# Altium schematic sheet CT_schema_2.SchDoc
size 461 x 327 mm
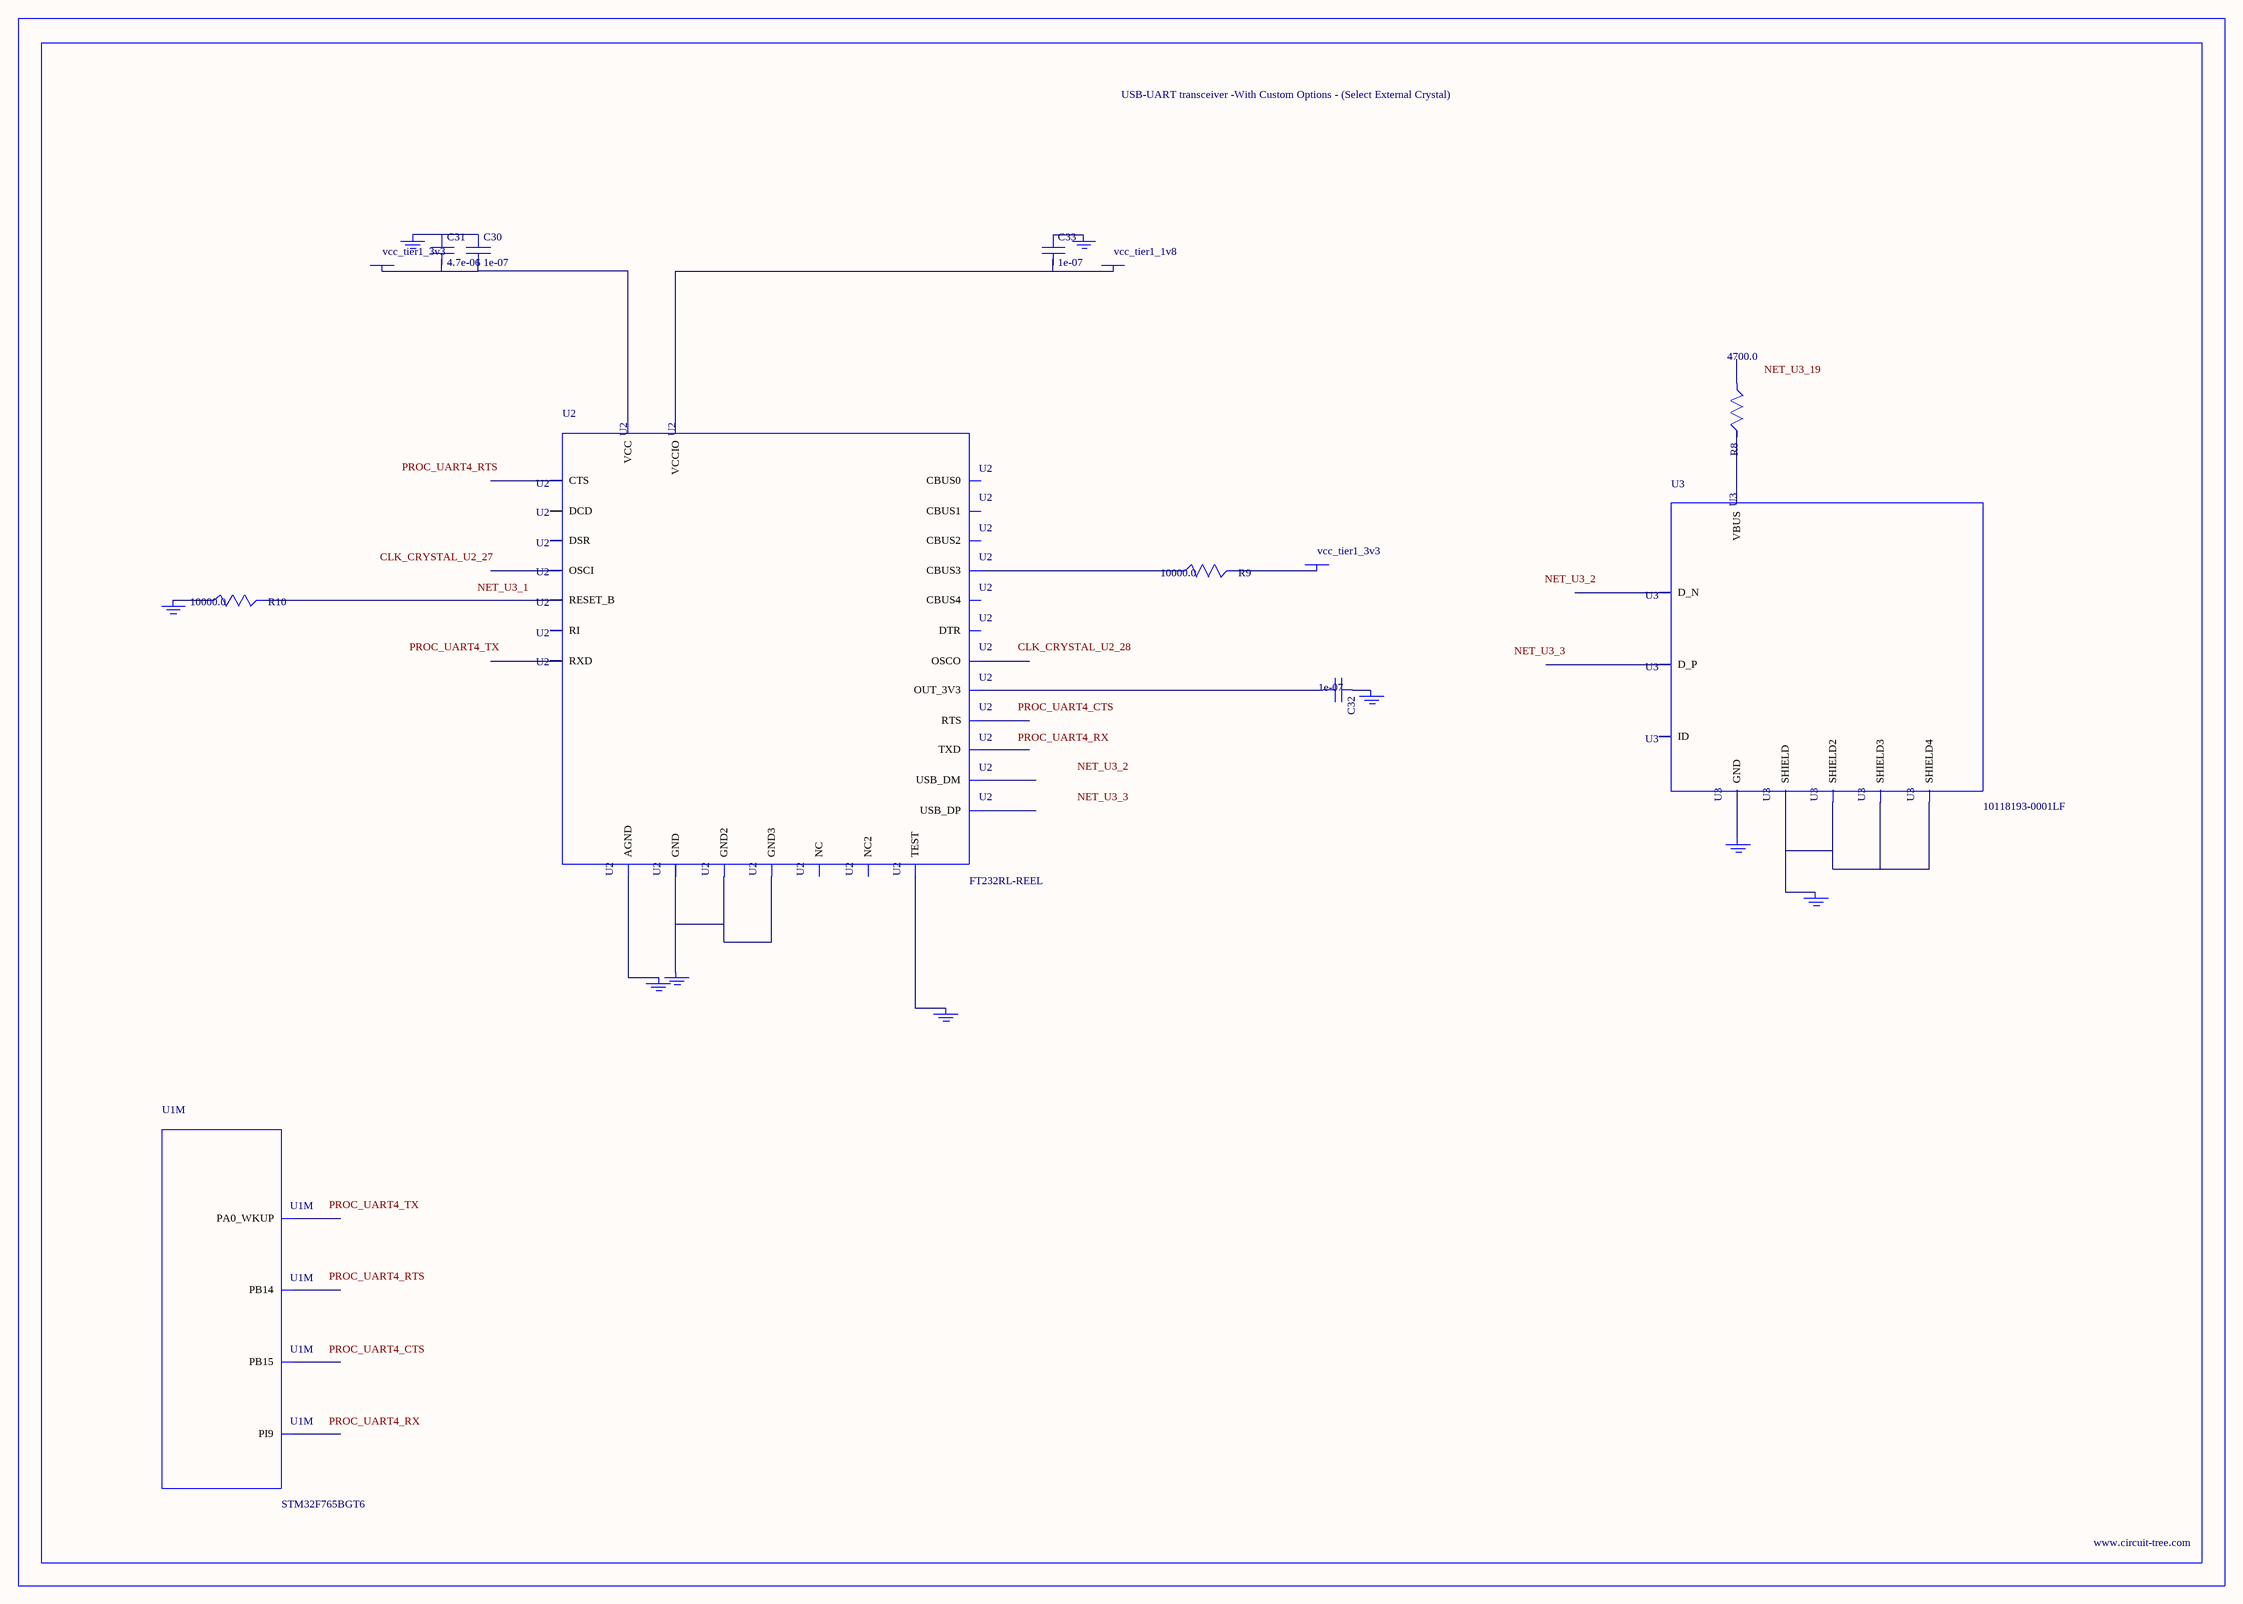
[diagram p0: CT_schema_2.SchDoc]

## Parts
BORDER1  (no value)
C30  1e-07  [C0402]
C31  4.7e-06  [C0805]
C32  1e-07  [C0402]
C33  1e-07  [C0402]
GND_INSTANCE_1_0  (no value)
GND_INSTANCE_1_1  (no value)
GND_INSTANCE_1_2  (no value)
GND_INSTANCE_1_3  (no value)
GND_INSTANCE_1_4  (no value)
GND_INSTANCE_1_5  (no value)
GND_INSTANCE_1_6  (no value)
GND_INSTANCE_1_7  (no value)
GND_INSTANCE_1_8  (no value)
POWER_INSTANCE_1_0  vcc_tier1_1v8
POWER_INSTANCE_1_1  vcc_tier1_3v3
POWER_INSTANCE_1_2  vcc_tier1_3v3
R8  4700.0  [R0603]
R9  10000.0  [R0603]
R10  10000.0  [R0603]
U1  STM32F765BGT6  [LQFP208]  (part M of 16)
U2  FT232RL-REEL  [SSOP-28]
U3  10118193-0001LF  [FCI_10118193-0001LF]

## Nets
NetC30_1: C30.1 C31.1 GND_INSTANCE_1_3.0(GND)
NetC30_2: C30.2 C31.2 POWER_INSTANCE_1_2.0(PWR) U2.20(VCC)
NetC32_1: C32.1 GND_INSTANCE_1_1.0(GND)
NetC32_2: C32.2 U2.17(OUT_3V3)
NetC33_1: C33.1 GND_INSTANCE_1_0.0(GND)
NetC33_2: C33.2 POWER_INSTANCE_1_0.0(PWR) U2.4(VCCIO)
NetGND_INSTANCE_1_2_0: GND_INSTANCE_1_2.0(GND) R10.1
NetGND_INSTANCE_1_4_0: GND_INSTANCE_1_4.0(GND) U2.25(AGND)
NetGND_INSTANCE_1_5_0: GND_INSTANCE_1_5.0(GND) U2.26(TEST)
NetGND_INSTANCE_1_6_0: GND_INSTANCE_1_6.0(GND) U2.7(GND) U2.18(GND2) U2.21(GND3)
NetGND_INSTANCE_1_7_0: GND_INSTANCE_1_7.0(GND) U3.6(SHIELD) U3.7(SHIELD2) U3.8(SHIELD3) U3.9(SHIELD4)
NetGND_INSTANCE_1_8_0: GND_INSTANCE_1_8.0(GND) U3.5(GND)
NetPOWER_INSTANCE_1_1_0: POWER_INSTANCE_1_1.0(PWR) R9.2
NetR8_2: R8.2 U3.1(VBUS)
NetR9_1: R9.1 U2.14(CBUS3)
NetR10_2: R10.2 U2.19(RESET_B)

Not connected (* = marked no-connect by the designer): R8 1; U1 11(PI9) 43(PA0_WKUP) 106(PB14) 107(PB15); U2 1(TXD) 2(DTR) 3(RTS) 5(RXD) 6(RI) 8(NC) 9(DSR) 10(DCD) 11(CTS) 12(CBUS4) 13(CBUS2) 15(USB_DP) 16(USB_DM) 22(CBUS1) 23(CBUS0) 24(NC2) 27(OSCI) 28(OSCO); U3 2(D_N) 3(D_P) 4(ID)

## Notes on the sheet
- Labels drawn without touching a wire or pin: CLK_CRYSTAL_U2_27, CLK_CRYSTAL_U2_28, NET_U3_1, NET_U3_2, NET_U3_3, NET_U3_19, PROC_UART4_CTS, PROC_UART4_RTS, PROC_UART4_RX, PROC_UART4_TX

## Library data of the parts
BORDER1 = BORDER_PAGE1
C30 C32 C33 = C0402C104K3RACTU
C31 = C0805C475K4RACTU
GND_INSTANCE_1_0-GND_INSTANCE_1_8 = GND
POWER_INSTANCE_1_0-POWER_INSTANCE_1_2 = PWR
R8 = RC0603JR-074K7L
R9 R10 = RC0603JR-0710KL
